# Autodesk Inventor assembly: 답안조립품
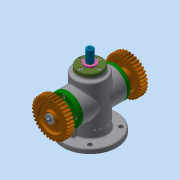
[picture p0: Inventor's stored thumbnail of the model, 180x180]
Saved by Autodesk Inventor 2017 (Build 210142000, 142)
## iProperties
Part Number: 답안조립품
Material: 일반
Document SubType Name: Assembly
Designer: mrc
Mass: 1364.2 g
Surface Area: 1735.34 cm^2
Volume: 520.939 cm^3
Density: 2.61874 g/cm^3
Author: mrc
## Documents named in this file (17)
- C:\Users\mrc\Desktop\600606V1021\답안조립품.iam
- C:\Users\mrc\Desktop\600606V1021\본체.ipt
- C:\Users\mrc\Desktop\600606V1021\멈춤링.ipt
- C:\Users\mrc\Desktop\600606V1021\베어링 6203.ipt
- C:\Users\mrc\Desktop\600606V1021\볼트 M4.ipt
- C:\Users\mrc\Desktop\600606V1021\부시.ipt
- C:\Users\mrc\Desktop\600606V1021\스퍼기어.ipt
- C:\Users\mrc\Desktop\600606V1021\스프링와셔.ipt
- C:\Users\mrc\Desktop\600606V1021\스프링조립용 와셔.ipt
- C:\Users\mrc\Desktop\600606V1021\슬라이더.ipt
- C:\Users\mrc\Desktop\600606V1021\오일 실 17 30 8.ipt
- C:\Users\mrc\Desktop\600606V1021\커버 A.ipt
- C:\Users\mrc\Desktop\600606V1021\커버 B.ipt
- C:\Users\mrc\Desktop\600606V1021\키 4x4x12.ipt
- C:\Users\mrc\Desktop\600606V1021\편심축.ipt
- C:\Users\mrc\Desktop\600606V1021\평와셔.ipt
- C:\Users\mrc\Desktop\600606V1021\가변스프링.ipt
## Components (1 placed, 1 different names)
1. 가변스프링:1
